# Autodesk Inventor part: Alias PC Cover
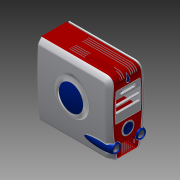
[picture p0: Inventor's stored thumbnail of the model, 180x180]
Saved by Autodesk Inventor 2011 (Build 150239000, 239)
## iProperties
Created: 2007-02
Part Number: Alias PC Cover
Document SubType Name: Modeling
Designer: floress
Density: 1 g/cm^3
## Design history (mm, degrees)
feature "Right Side"
feature "Left Side"
body "Srf1"
body "Srf2"
